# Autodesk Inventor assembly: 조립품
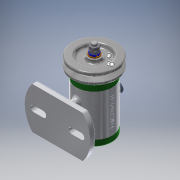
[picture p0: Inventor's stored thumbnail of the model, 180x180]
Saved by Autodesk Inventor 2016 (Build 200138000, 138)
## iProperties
Created: 2017-12
Part Number: 조립품
Material: 일반
Document SubType Name: Assembly
Designer: 605-03
Author: 605-03
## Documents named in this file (14)
- C:\Users\605-03\Desktop\471207V1028\조립품.iam
- C:\Users\605-03\Desktop\471207V1028\본체.ipt
- C:\Users\605-03\Desktop\471207V1028\V벨트풀리.ipt
- C:\Users\605-03\Desktop\471207V1028\고무캡.ipt
- C:\Users\605-03\Desktop\471207V1028\너트 M 8.ipt
- C:\Users\605-03\Desktop\471207V1028\뒤커버.ipt
- C:\Users\605-03\Desktop\471207V1028\베어링 15 x 32 x 9.ipt
- C:\Users\605-03\Desktop\471207V1028\볼트 M4 x 12.ipt
- C:\Users\605-03\Desktop\471207V1028\스프링와셔 8.ipt
- C:\Users\605-03\Desktop\471207V1028\앞커버.ipt
- C:\Users\605-03\Desktop\471207V1028\오일 실 15 25 7.ipt
- C:\Users\605-03\Desktop\471207V1028\와셔 8x17.ipt
- C:\Users\605-03\Desktop\471207V1028\축.ipt
- C:\Users\605-03\Desktop\471207V1028\키 3 x 3 x 12.ipt
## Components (2 placed, 2 different names)
1. V벨트풀리:1
2. 고무캡:1
